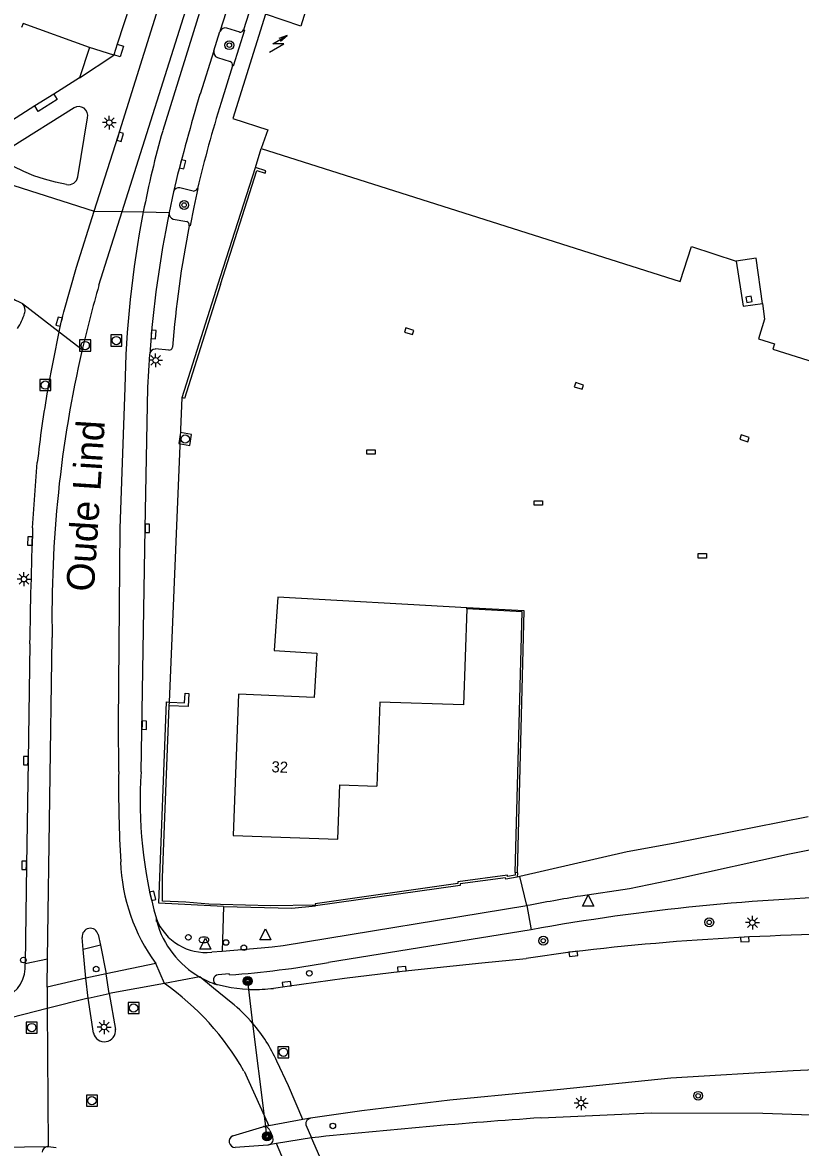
# Model space of a CAD drawing. Extents: x 132999 to 136000, y 398499 to 400501.
# Drawn here: x 133982.2 to 134052.2, y 398698.2 to 398799.5 of the extents above; entities that cross this region are included whole.
import ezdxf

# ---------------------------------------------------------------- set-up
doc = ezdxf.new("R2010")
doc.units = 0
for name, color, linetype in [('gg-afsc-hekwerk', 7, 'Continuous'), ('gg-afsc-muur', 7, 'Continuous'), ('gg-anno-huisnummerreeks BGT', 7, 'Continuous'), ('gg-anno-openbare ruimte label', 7, 'Continuous'), ('gg-bbg-hoofdgebouw', 7, 'Continuous'), ('gg-bbg-onder overbouw', 7, 'Continuous'), ('gg-bbg-pand overbouw', 7, 'Continuous'), ('gg-bbg-pilaar onder overbouw', 7, 'Continuous'), ('gg-bbg-tussenscheiding', 7, 'Continuous'), ('gg-knt-verharding', 7, 'Continuous'), ('gg-knt-verharding nz', 7, 'Continuous'), ('gt-grn-weggrens', 7, 'Continuous'), ('gt-knt-lijn portaal', 7, 'Continuous'), ('gt-symb-boom', 7, 'Continuous'), ('gt-symb-brandkraan', 7, 'Continuous'), ('gt-symb-drukknoppaal', 7, 'Continuous'), ('gt-symb-kolk', 7, 'Continuous'), ('gt-symb-kolk center center', 7, 'Continuous'), ('gt-symb-lichtmast', 7, 'Continuous'), ('gt-symb-portaalmast', 7, 'Continuous'), ('gt-symb-rioolschacht', 7, 'Continuous'), ('gt-symb-trafo symbool', 7, 'Continuous'), ('gt-symb-verkeersbordpaal', 7, 'Continuous'), ('gt-symb-verkeersregelinstallatiepaal', 7, 'Continuous'), ('gt-symb-waterafsluiter', 7, 'Continuous')]:
    doc.layers.add(name, color=color, linetype=linetype)

# ---------------------------------------------------------------- blocks, each defined once
blk = doc.blocks.new('gt0-PORTM')
at = {"layer": 'gt-symb-portaalmast'}
for radius in [0.4, 0.33, 0.27, 0.21, 0.15]:
    blk.add_circle((0, 0), radius, dxfattribs=at)
blk = doc.blocks.new('gt0-RS')
at = {"layer": 'gt-symb-rioolschacht'}
blk.add_lwpolyline([(-0.5, -0.5), (0.5, -0.5), (0.5, 0.5), (-0.5, 0.5)], close=True, dxfattribs=at)
blk.add_circle((0, 0), 0.375, dxfattribs=at)
blk = doc.blocks.new('gt0-KOLK')
at = {"layer": 'gt-symb-kolk'}
blk.add_lwpolyline([(0, 0), (0.37, 0), (0.37, 0.4), (-0.38, 0.4), (-0.38, 0), (0, 0)], dxfattribs=at)
blk = doc.blocks.new('gt0-DPAAL')
at = {"layer": 'gt-symb-drukknoppaal'}
blk.add_circle((0, 0), 0.25, dxfattribs=at)
blk = doc.blocks.new('gt0-WAFSL')
at = {"layer": 'gt-symb-waterafsluiter'}
for p, q in [((-0.5, -0.33), (0, 0.67)), ((0, 0.67), (0.5, -0.33)), ((0.5, -0.33), (-0.5, -0.33))]:
    blk.add_line(p, q, dxfattribs=at)
blk = doc.blocks.new('gt0-VIPAAL')
at = {"layer": 'gt-symb-verkeersregelinstallatiepaal'}
blk.add_circle((0, 0), 0.25, dxfattribs=at)
blk = doc.blocks.new('gt0-BR')
at = {"layer": 'gt-symb-brandkraan'}
for centre, radius, start, end in [((-0.24, 0), 0.206, 107.5669, 252.4331), ((0.6, -2.66), 3, 106.892, 107.5669), ((0, -0.69), 0.938, 73.108, 106.892), ((-0.6, -2.66), 3, 72.4331, 73.108), ((0.24, 0), 0.206, 287.567, 72.4331), ((0.6, 2.66), 3, 252.4331, 253.108), ((0, 0.69), 0.938, 253.108, 286.8921), ((-0.6, 2.66), 3, 286.8921, 287.567)]:
    blk.add_arc(centre, radius, start, end, dxfattribs=at)
blk = doc.blocks.new('gt0-LMAST')
at = {"layer": 'gt-symb-lichtmast'}
for p, q in [((-0.18, 0.17), (-0.45, 0.44)), ((-0.01, 0.25), (-0.01, 0.62)), ((0.17, 0.17), (0.44, 0.44)), ((-0.26, 0), (-0.63, 0)), ((-0.18, -0.18), (-0.45, -0.45)), ((-0.01, -0.25), (-0.01, -0.63)), ((0.44, -0.45), (0.17, -0.18)), ((0.24, 0), (0.62, 0))]:
    blk.add_line(p, q, dxfattribs=at)
blk.add_circle((-0.01, 0), 0.25, dxfattribs=at)
blk = doc.blocks.new('gt0-BOOM')
at = {"layer": 'gt-symb-boom'}
for radius in [0.4, 0.2]:
    blk.add_circle((0, 0), radius, dxfattribs=at)
blk = doc.blocks.new('gt0-HSP')
at = {"layer": 'gt-symb-trafo symbool'}
for points in [[(0.77, 0.75), (-0.53, 0), (0.47, 0), (-0.83, -0.75)], [(-0.22, -0.24), (-0.83, -0.75), (-0.08, -0.48)]]:
    blk.add_lwpolyline(points, dxfattribs=at)
blk = doc.blocks.new('gt0-KOLKCC')
at = {"layer": 'gt-symb-kolk center center'}
blk.add_lwpolyline([(-0.38, 0.2), (0.38, 0.2), (0.38, -0.2), (-0.38, -0.2)], close=True, dxfattribs=at)
blk = doc.blocks.new('gt0-VPAAL')
at = {"layer": 'gt-symb-verkeersbordpaal'}
blk.add_circle((0, 0), 0.25, dxfattribs=at)

msp = doc.modelspace()

# ---------------------------------------------------------------- linework, layer by layer
at = {"layer": 'gg-afsc-hekwerk'}
for points in [[(133994.76, 398720.36), (133994.77, 398722.49), (133995.38, 398737.95)], [(134000, 398720.05), (133998.94, 398720.08), (133996.88, 398720.27), (133994.76, 398720.36)], [(134008.54, 398719.98), (134004.5, 398719.94), (134000, 398720.05)]]:
    msp.add_lwpolyline(points, dxfattribs=at)
at = {"layer": 'gg-afsc-muur'}
for p, q in [((133987.29, 398794.48), (133990.37, 398796.52)), ((134000, 398776.59), (134003.13, 398786.42)), ((133996.53, 398765.69), (134000, 398776.59)), ((133995.38, 398737.95), (133995.39, 398738.27)), ((134026.74, 398722.91), (134026.54, 398722.92)), ((134026.74, 398722.91), (134026.73, 398722.51)), ((134008.55, 398719.93), (134008.54, 398719.98))]:
    msp.add_line(p, q, dxfattribs=at)
for points in [[(134000, 398775.87), (134003.27, 398786.14), (134004.01, 398785.9), (134004.08, 398786.11), (134003.13, 398786.42)], [(134000, 398775.87), (133996.74, 398765.62), (133996.53, 398765.69)], [(134026.74, 398722.91), (134027.36, 398746.48), (134022.19, 398746.77)], [(134026.54, 398722.92), (134027.16, 398746.39), (134022.19, 398746.68)], [(133995.39, 398738.27), (133996.76, 398738.21), (133996.8, 398739.07), (133997.13, 398739.06), (133997.08, 398737.88), (133995.38, 398737.95)], [(134026.54, 398722.92), (134026.54, 398722.68), (134025.86, 398722.57), (134025.84, 398722.68), (134021.36, 398722.08), (134021.38, 398721.93), (134008.51, 398720.12), (134008.54, 398719.98)], [(134026.73, 398722.51), (134025.7, 398722.34), (134025.68, 398722.46), (134021.58, 398721.9), (134021.59, 398721.76), (134008.55, 398719.93)]]:
    msp.add_lwpolyline(points, dxfattribs=at)
at = {"layer": 'gg-bbg-hoofdgebouw'}
for p, q in [((133991.84, 398801.07), (133990.69, 398797.51)), ((133990.69, 398797.51), (133990.38, 398796.55)), ((133988.19, 398797.21), (133987.29, 398794.48)), ((133990.37, 398796.52), (133988.19, 398797.21)), ((133990.38, 398796.55), (133990.37, 398796.52)), ((133987.29, 398794.48), (133984.97, 398793.02)), ((133984.97, 398793.02), (133983.27, 398791.95)), ((133983.27, 398791.95), (133979.12, 398789.33)), ((134022.19, 398746.77), (134005.15, 398747.72)), ((134022.19, 398746.68), (134022.19, 398746.77))]:
    msp.add_line(p, q, dxfattribs=at)
for points in [[(134010.13, 398815.35), (134006.22, 398803), (134008.2, 398802.25), (134007.23, 398799.13), (134004.05, 398800.21)], [(134004.05, 398800.21), (134001.1, 398790.81), (134004.26, 398789.81), (134003.67, 398788.12)], [(134003.67, 398788.12), (134041.41, 398776.14), (134042.41, 398779.29), (134046.44, 398777.99)], [(134048.82, 398774.15), (134049.01, 398772.75), (134048.46, 398770.98), (134049.89, 398770.53), (134049.75, 398770.06), (134057.11, 398767.73)], [(134005.15, 398747.72), (134004.84, 398742.93), (134008.68, 398742.68), (134008.42, 398738.68), (134001.61, 398739), (134001.13, 398726.26), (134010.57, 398725.93), (134010.74, 398730.83), (134014.08, 398730.71)], [(134022.19, 398746.68), (134021.88, 398738.02), (134014.35, 398738.28), (134014.08, 398730.71)]]:
    msp.add_lwpolyline(points, dxfattribs=at)
at = {"layer": 'gg-bbg-onder overbouw'}
msp.add_lwpolyline([(134048.82, 398774.15), (134048.24, 398778.24), (134046.44, 398777.99)], dxfattribs=at)
at = {"layer": 'gg-bbg-pand overbouw'}
for p, q in [((134046.44, 398777.99), (134047.07, 398773.91)), ((134047.07, 398773.91), (134048.82, 398774.15))]:
    msp.add_line(p, q, dxfattribs=at)
at = {"layer": 'gg-bbg-pilaar onder overbouw'}
msp.add_lwpolyline([(134047.33, 398774.74), (134047.4, 398774.26), (134047.88, 398774.34), (134047.81, 398774.82), (134047.33, 398774.74)], dxfattribs=at)
at = {"layer": 'gg-bbg-tussenscheiding'}
msp.add_lwpolyline([(133988.19, 398797.21), (133982.21, 398799.38), (133982.07, 398799.01)], dxfattribs=at)
at = {"layer": 'gg-knt-verharding'}
for p, q in [((134005.55, 398809.89), (134002.07, 398798.8)), ((133999.4, 398796.91), (133999.94, 398798.64)), ((134001.72, 398798.6), (134000.57, 398798.95)), ((133999.4, 398796.91), (133998.15, 398793.01)), ((133999.71, 398796.32), (134000.87, 398795.96)), ((134001.07, 398795.56), (134000.04, 398792.26)), ((133986.8, 398791.79), (133981.07, 398788.17)), ((133987.13, 398785.57), (133988.01, 398790.89)), ((134003.13, 398786.42), (134003.67, 398788.12)), ((133995.88, 398784.72), (133995.77, 398784.22)), ((133997.54, 398784.29), (133996.34, 398784.58)), ((133995.77, 398784.22), (133995.37, 398782.36)), ((133995.73, 398781.77), (133996.95, 398781.56)), ((133984.43, 398766.45), (133985.46, 398771.61)), ((133995.34, 398769.97), (133994.12, 398770.07)), ((133995.39, 398738.28), (133996.53, 398765.69)), ((133983.07, 398753.97), (133983.48, 398759.84)), ((133995.39, 398738.27), (133995.39, 398738.28)), ((134026.97, 398722.56), (134026.73, 398722.51)), ((134000.26, 398719.86), (134000.15, 398715.86)), ((134027.58, 398719.96), (134027.97, 398717.78)), ((134027.97, 398717.78), (134009.73, 398714.84)), ((133987.63, 398716.01), (133987.53, 398717.08)), ((133988.97, 398717.35), (133989.18, 398716.38)), ((133989.18, 398716.38), (133987.63, 398716.01)), ((133987.85, 398713.43), (133987.63, 398716.01)), ((133989.18, 398716.38), (133989.68, 398713.8)), ((133999.2, 398715.78), (134000.15, 398715.86)), ((134031.71, 398715.79), (134027.54, 398715.18)), ((133989.68, 398713.8), (133987.85, 398713.43)), ((134002.53, 398712.4), (134002.75, 398712.39)), ((133988.06, 398711.61), (133989.95, 398712.03)), ((133988.55, 398708.48), (133988.06, 398711.61)), ((133989.95, 398712.03), (133990.52, 398708.81)), ((134001.1, 398699.23), (134003.82, 398700.05)), ((134003.82, 398700.05), (134003.88, 398700.06)), ((134004.44, 398699.71), (134004.68, 398699.16)), ((134007.68, 398700.23), (134008.2, 398699.05)), ((133984.4, 398698.25), (133984.48, 398698.26)), ((133984.48, 398698.26), (133985.18, 398698.16)), ((134004.27, 398698.4), (134001.32, 398698.19)), ((134004.36, 398698.42), (134004.27, 398698.4))]:
    msp.add_line(p, q, dxfattribs=at)
for points in [[(133988.62, 398782.49), (133990.76, 398789.22), (133999.51, 398817.15), (134004.13, 398831.89), (134008.15, 398844.74)], [(134003.88, 398811.2), (134000.5, 398800.41), (133999.94, 398798.64)], [(134002.07, 398798.8), (134002.15, 398798.78), (134001.13, 398795.54), (134001.07, 398795.56)], [(133990.69, 398797.51), (133991.24, 398797.33), (133990.94, 398796.37), (133990.38, 398796.55)], [(133984.97, 398793.02), (133985.28, 398792.53), (133983.58, 398791.46), (133983.27, 398791.95)], [(133986.13, 398784.89), (133985.12, 398785.08), (133984.14, 398785.35), (133983.18, 398785.67), (133982.26, 398786.06), (133981.35, 398786.49), (133981.07, 398786.73), (133980.8, 398786.98)], [(133997.91, 398784.53), (133997.96, 398784.52), (133997.6, 398782.84), (133997.27, 398781.15), (133997.17, 398781.17)], [(133985.46, 398771.61), (133985.65, 398772.48), (133985.8, 398773.05), (133985.89, 398773.42), (133987.02, 398777.45), (133988.62, 398782.49)], [(133992.85, 398732), (133993.2, 398753.91), (133993.45, 398766.6), (133993.62, 398769.61)], [(133982.8, 398743.52), (133982.65, 398733), (133982.5, 398723.58), (133982.4, 398714.75)], [(134000.26, 398719.86), (133994.45, 398720.17), (133995.13, 398738.29), (133995.39, 398738.28)], [(134052.92, 398727.94), (134040.77, 398725.54), (134036.63, 398724.8), (134026.97, 398722.56)], [(134032.43, 398720.82), (134036.84, 398721.49), (134041.18, 398722.39), (134051.24, 398724.62), (134053.49, 398725.07)], [(134000.15, 398715.86), (134003.65, 398716.16), (134004.64, 398716.25), (134005.64, 398716.37), (134027.58, 398719.96)], [(134000.26, 398719.86), (134006.41, 398719.73), (134008.55, 398719.93)], [(134004.77, 398712.51), (134005.99, 398712.69), (134011.16, 398713.42), (134016.35, 398714.04), (134023.54, 398714.81), (134027.54, 398715.18)], [(134000.8, 398713.72), (134000.77, 398713.82), (133999.78, 398713.73)], [(134002.53, 398712.4), (134001.97, 398712.43), (134000.96, 398712.54), (133999.71, 398712.82), (133999.62, 398712.85)], [(134051.57, 398705.09), (134040.55, 398704.43), (134030.63, 398703.4), (134020.66, 398702.43), (134012.71, 398701.49), (134008.09, 398700.82)], [(134028.87, 398700.85), (134038.8, 398701.31), (134048.84, 398701.27), (134059.26, 398700.92), (134061, 398700.8)], [(134003.88, 398700.06), (134003.98, 398700.06), (134004.07, 398700.05)]]:
    msp.add_lwpolyline(points, dxfattribs=at)
for centre, radius, start, end in [((134000.42, 398798.47), 0.509, 72.907, 160.5138), ((134001.76, 398798.93), 0.333, 262.7892, 338.2702), ((133999.87, 398796.78), 0.489, 164.9476, 250.7217), ((134000.68, 398795.62), 0.392, 351.5094, 61.3924), ((134184.83, 398737.43), 194.79, 163.4206, 165.9487), ((133987.21, 398791.08), 0.82, 347.0181, 120.2616), ((134138.38, 398750), 144.65, 163.0132, 166.1895), ((133986.32, 398785.68), 0.817, 256.6412, 351.8185), ((133996.25, 398784.08), 0.508, 79.6016, 163.7127), ((133997.54, 398784.69), 0.401, 270.0025, 336.4384), ((134090.99, 398762.72), 97.62, 168.3928, 175.9537), ((133995.87, 398782.26), 0.508, 168.8393, 254.5386), ((133996.83, 398781.23), 0.346, 350.2532, 70.5738), ((134094.16, 398762.24), 98.82, 168.9554, 175.3571), ((133996.7, 398803.61), 32.85, 233.8477, 243.7244), ((133976.99, 398774.93), 5.6, 327.3215, 343.1386), ((133981.6, 398773.57), 0.799, 340.3569, 46.5376), ((133995.35, 398770.28), 0.317, 267.8621, 351.8181), ((133994.12, 398769.56), 0.506, 89.6158, 174.819), ((134080.04, 398749.44), 97.11, 169.9165, 173.8548), ((134480.8, 398735.93), 498.06, 177.9246, 179.1277), ((134031.41, 398729.29), 38.66, 175.982, 195.8184), ((134114.31, 398245.92), 481.9, 99.782, 100.3685), ((134062.33, 398526.91), 193.94, 91.1566, 100.2057), ((133998.63, 398720.48), 4.74, 201.3693, 276.8726), ((133988.26, 398717.18), 0.732, 13.3486, 187.934), ((134059.35, 398482.58), 234.84, 89.4183, 96.7589), ((133979.3, 398714.49), 3.11, 293.2708, 4.7692), ((133994.73, 398798.28), 84.78, 274.1037, 280.1905), ((133999.81, 398713.27), 0.462, 93.7239, 245.2885), ((134002.69, 398731.38), 18.99, 270.1609, 276.2834), ((133989.53, 398708.69), 1, 191.8261, 7.1739), ((134059.03, 398509.87), 195.36, 89.0561, 92.1886), ((134008.22, 398700.29), 0.544, 103.0083, 186.45), ((134069.95, 398108.17), 594.1, 93.96567, 95.96663), ((134001.31, 398698.73), 0.543, 112.7255, 270.5697), ((134003.94, 398699.53), 0.532, 19.915, 75.9232), ((133984.45, 398697.72), 0.536, 95.273, 175.4314), ((134004.23, 398698.91), 0.508, 284.7406, 29.5162)]:
    msp.add_arc(centre, radius, start, end, dxfattribs=at)
at = {"layer": 'gg-knt-verharding nz'}
for p, q in [((133991.14, 398782.44), (134010.61, 398844.26)), ((134011.37, 398842.92), (133994.79, 398789.73)), ((133989.04, 398775.8), (133991.14, 398782.44)), ((133984.41, 398715.15), (133984.83, 398744.09)), ((133994.24, 398718.51), (133994.22, 398718.75)), ((133984.37, 398712.61), (133984.41, 398715.15)), ((133994.16, 398714.75), (133989.68, 398713.8)), ((133987.85, 398713.43), (133984.37, 398712.61)), ((133988.06, 398711.61), (133987.85, 398713.43)), ((133989.95, 398712.03), (133989.68, 398713.8)), ((133998.12, 398713.53), (133994.95, 398712.95)), ((133984.37, 398712.61), (133984.38, 398710.69)), ((133994.95, 398712.95), (133989.95, 398712.03)), ((133988.06, 398711.61), (133984.38, 398710.69)), ((133984.38, 398710.69), (133980.01, 398709.59)), ((133984.38, 398710.69), (133984.48, 398698.26)), ((134002.11, 398705.05), (134003.95, 398701.01)), ((134003.95, 398701.01), (134004.35, 398700.14)), ((134007.4, 398700.7), (134004.35, 398700.14)), ((134008.09, 398700.82), (134007.4, 398700.7)), ((134004.07, 398700.09), (134003.88, 398700.06)), ((134004.35, 398700.14), (134004.07, 398700.09)), ((133984.4, 398698.25), (133980.25, 398698.18)), ((134005.04, 398698.53), (134004.36, 398698.42)), ((134008.2, 398699.05), (134005.04, 398698.53)), ((134009.41, 398688.24), (134005.04, 398698.53)), ((134011.88, 398690.57), (134008.2, 398699.05))]:
    msp.add_line(p, q, dxfattribs=at)
for points in [[(133991.37, 398766.6), (133990.92, 398753.91), (133990.76, 398736.35), (133990.81, 398732.03)], [(134000.96, 398711.22), (133999.37, 398712.52), (133998.12, 398713.53)], [(134007.4, 398700.7), (134006.13, 398703.74), (134005.07, 398705.94)]]:
    msp.add_lwpolyline(points, dxfattribs=at)
for centre, radius, start, end in [((134081.36, 398765.12), 90, 164.1342, 168.927), ((134081.37, 398765.12), 90.01, 168.929, 179.0602), ((134090.89, 398746.18), 106.07, 163.7855, 167.0179), ((134091.14, 398746.11), 106.33, 167.0096, 181.0861), ((134103.57, 398730.49), 112.76, 179.2193, 183.3567), ((134007.43, 398724.47), 16.45, 182.024, 216.2211), ((134002.29, 398720.76), 8.35, 195.5906, 240.04), ((134002.14, 398720.43), 7.99, 239.7959, 251.6216), ((133980.83, 398692.96), 24.47, 29.6169, 54.7502), ((133992.15, 398700.12), 14.17, 40.5826, 51.568), ((133992.11, 398700.08), 14.23, 24.3157, 40.5765)]:
    msp.add_arc(centre, radius, start, end, dxfattribs=at)
at = {"layer": 'gt-grn-weggrens'}
for p, q in [((133980.62, 398785.03), (133988.62, 398782.49)), ((133988.62, 398782.49), (133991.14, 398782.44)), ((133991.14, 398782.44), (133993.03, 398782.41)), ((133993.03, 398782.41), (133995.37, 398782.36)), ((133982.15, 398774.16), (133985.46, 398771.61)), ((133985.46, 398771.61), (133987.53, 398770.01)), ((134027.58, 398719.96), (134026.97, 398722.56)), ((133982.4, 398714.75), (133984.41, 398715.15)), ((133994.95, 398712.95), (133994.16, 398714.75))]:
    msp.add_line(p, q, dxfattribs=at)
at = {"layer": 'gt-knt-lijn portaal'}
for p, q in [((134002.53, 398712.4), (134002.44, 398713.16)), ((134002.91, 398709.34), (134002.53, 398712.4)), ((134003.95, 398701.01), (134002.91, 398709.34)), ((134004.07, 398700.09), (134003.95, 398701.01)), ((134004.07, 398700.05), (134004.07, 398700.09)), ((134004.18, 398699.18), (134004.07, 398700.05))]:
    msp.add_line(p, q, dxfattribs=at)

# ---------------------------------------------------------------- block references
at = {"layer": 'gt-symb-boom'}
for p in [(134000.79, 398797.42), (133996.72, 398783.03), (134044.02, 398718.45), (134029.07, 398716.79), (134043.02, 398702.83)]:
    msp.add_blockref('gt0-BOOM', p, dxfattribs=at)
at = {"layer": 'gt-symb-brandkraan'}
msp.add_blockref('gt0-BR', (133998.5, 398716.87), dxfattribs=at)
at = {"layer": 'gt-symb-drukknoppaal'}
for p in [(134002.09, 398716.16), (133982.23, 398715.05)]:
    msp.add_blockref('gt0-DPAAL', p, dxfattribs=at)
at = {"layer": 'gt-symb-kolk'}
for p, rotation in [((133990.76, 398789.22), -107.64383243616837), ((133996.39, 398786.74), -104.36115029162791), ((133985.65, 398772.48), 75.34721260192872), ((133993.76, 398771.39), -94.56458943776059), ((134017.04, 398771.86), 162.36228444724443), ((134032.34, 398766.94), 161.81873102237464), ((134047.26, 398762.22), 161.9999254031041), ((133993.2, 398753.91), -90.89580410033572), ((133983.03, 398752.78), 87.99836919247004), ((133992.92, 398736.2), -90.93614861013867), ((133982.65, 398733), 89.18488754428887), ((133982.5, 398723.58), 89.10419589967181), ((133993.7, 398720.78), -76.14579020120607), ((134047.21, 398717.11), -176.44511133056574), ((134031.75, 398715.8), -173.28012011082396), ((134016.35, 398714.04), 6.136997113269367), ((134005.99, 398712.69), 7.364256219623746)]:
    msp.add_blockref('gt0-KOLK', p, dxfattribs=dict(at, rotation=rotation))
at = {"layer": 'gt-symb-kolk center center'}
for p in [(134013.56, 398760.79), (134028.63, 398756.2), (134043.4, 398751.45)]:
    msp.add_blockref('gt0-KOLKCC', p, dxfattribs=at)
at = {"layer": 'gt-symb-lichtmast'}
for p in [(133989.98, 398790.45), (133994.16, 398769.05), (133982.29, 398749.35), (134047.92, 398718.42), (133989.51, 398709.02), (134032.48, 398702.18)]:
    msp.add_blockref('gt0-LMAST', p, dxfattribs=at)
at = {"layer": 'gt-symb-portaalmast'}
for p in [(134002.44, 398713.16), (134004.18, 398699.18)]:
    msp.add_blockref('gt0-PORTM', p, dxfattribs=at)
at = {"layer": 'gt-symb-rioolschacht'}
for p in [(133990.61, 398770.83), (133987.8, 398770.38), (133984.21, 398766.82), (133992.16, 398710.73), (133982.99, 398708.97), (134005.66, 398706.75), (133988.41, 398702.39)]:
    msp.add_blockref('gt0-RS', p, dxfattribs=at)
at = {"layer": 'gt-symb-rioolschacht', "rotation": 170.15137761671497}
msp.add_blockref('gt0-RS', (133996.81, 398761.96), dxfattribs=at)
at = {"layer": 'gt-symb-trafo symbool', "rotation": 180}
msp.add_blockref('gt0-HSP', (134005.18, 398797.54), dxfattribs=at)
at = {"layer": 'gt-symb-verkeersbordpaal'}
msp.add_blockref('gt0-VPAAL', (134010.11, 398700.12), dxfattribs=at)
at = {"layer": 'gt-symb-verkeersregelinstallatiepaal'}
for p in [(133997.1, 398717.1), (134000.49, 398716.63), (133988.79, 398714.24), (134007.99, 398713.86)]:
    msp.add_blockref('gt0-VIPAAL', p, dxfattribs=at)
at = {"layer": 'gt-symb-waterafsluiter'}
for p in [(134033.11, 398720.23), (134004.04, 398717.19), (133998.63, 398716.36)]:
    msp.add_blockref('gt0-WAFSL', p, dxfattribs=at)

# ---------------------------------------------------------------- texts
at = {"layer": 'gg-anno-huisnummerreeks BGT'}
msp.add_text('32', height=1, rotation=357.8, dxfattribs=at).set_placement((134004.57, 398731.96))
at = {"layer": 'gg-anno-openbare ruimte label'}
msp.add_text('Oude Lind', height=2.5, rotation=86.3, dxfattribs=at).set_placement((133988.58, 398748.17))

doc.saveas('drawing.dxf')
